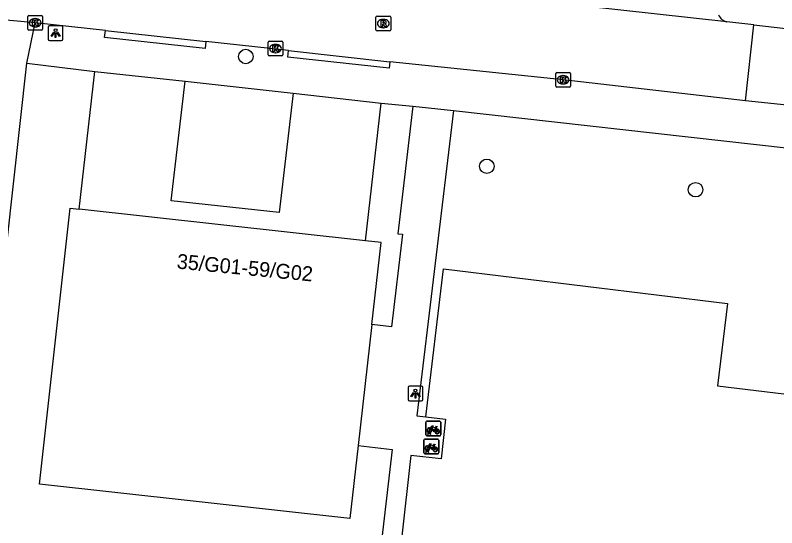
# Model space of a CAD drawing. Extents: x 161928 to 163055, y 386475 to 387428.
# Drawn here: x 162126.5 to 162177.9, y 387120.3 to 387155 of the extents above; entities that cross this region are included whole.
import ezdxf

# ---------------------------------------------------------------- set-up
doc = ezdxf.new("R2010")
doc.units = 0
for name, color, linetype in [('IMGEO_Boom', 7, 'Continuous'), ('IMGEO_Fietsenrek', 7, 'Continuous'), ('IMGEO_Groenvoorziening', 7, 'Continuous'), ('IMGEO_Kolk', 7, 'Continuous'), ('IMGEO_Lichtpunt', 7, 'Continuous'), ('IMGEO_Pand', 7, 'Continuous'), ('IMGEO_Pand_nummerreeks', 7, 'Continuous'), ('IMGEO_Rijbaan_lokaal_open', 7, 'Continuous'), ('IMGEO_Rioolput', 7, 'Continuous'), ('IMGEO_Voetpad_open', 7, 'Continuous')]:
    doc.layers.add(name, color=color, linetype=linetype)

msp = doc.modelspace()

# ---------------------------------------------------------------- linework, layer by layer
at = {"layer": 'IMGEO_Boom'}
for centre in [(162142.04, 387152.202), (162158.336, 387144.781), (162172.448, 387143.2)]:
    msp.add_circle(centre, 0.489, dxfattribs=at)
at = {"layer": 'IMGEO_Fietsenrek'}
for p, q in [((162154.218, 387126.633), (162154.218, 387127.474)), ((162154.218, 387127.474), (162154.218, 387126.633)), ((162154.293, 387127.558), (162155.134, 387127.558)), ((162155.134, 387127.558), (162154.293, 387127.558)), ((162155.218, 387127.483), (162155.218, 387126.642)), ((162155.218, 387126.642), (162155.218, 387127.483)), ((162154.905, 387127.107), (162154.941, 387127.012)), ((162155.143, 387126.558), (162154.302, 387126.558)), ((162154.302, 387126.558), (162155.143, 387126.558)), ((162154.345, 387126.642), (162154.384, 387126.802)), ((162154.379, 387126.642), (162154.345, 387126.642)), ((162154.414, 387126.79), (162154.379, 387126.642)), ((162154.456, 387126.814), (162154.455, 387126.818)), ((162154.497, 387126.642), (162154.463, 387126.784)), ((162154.487, 387126.825), (162154.488, 387126.818)), ((162154.495, 387126.788), (162154.53, 387126.642)), ((162154.53, 387126.642), (162154.497, 387126.642)), ((162154.083, 387125.421), (162154.083, 387126.262)), ((162154.083, 387126.262), (162154.083, 387125.421)), ((162154.158, 387126.346), (162154.999, 387126.346)), ((162154.999, 387126.346), (162154.158, 387126.346)), ((162155.083, 387126.271), (162155.083, 387125.43)), ((162155.083, 387125.43), (162155.083, 387126.271)), ((162154.21, 387125.43), (162154.249, 387125.59)), ((162154.244, 387125.43), (162154.21, 387125.43)), ((162154.279, 387125.578), (162154.244, 387125.43)), ((162154.321, 387125.602), (162154.32, 387125.606)), ((162154.362, 387125.43), (162154.328, 387125.572)), ((162154.352, 387125.613), (162154.353, 387125.606)), ((162154.36, 387125.576), (162154.395, 387125.43)), ((162154.395, 387125.43), (162154.362, 387125.43)), ((162154.77, 387125.895), (162154.806, 387125.8)), ((162155.008, 387125.346), (162154.167, 387125.346)), ((162154.167, 387125.346), (162155.008, 387125.346))]:
    msp.add_line(p, q, dxfattribs=at)
for points in [[(162154.552, 387127.032), (162154.5, 387126.942), (162154.46, 387126.917), (162154.461, 387126.964), (162154.516, 387127.058)], [(162154.531, 387127.084), (162154.626, 387127.248), (162154.712, 387127.234), (162154.714, 387127.225), (162154.658, 387127.214), (162154.631, 387127.169), (162154.887, 387127.128)], [(162154.827, 387126.84), (162154.777, 387126.84), (162154.586, 387127.091), (162154.567, 387127.059)], [(162154.874, 387127.103), (162154.617, 387127.144), (162154.6, 387127.115), (162154.767, 387126.895), (162154.874, 387127.103)], [(162154.922, 387127.005), (162154.892, 387127.082), (162154.783, 387126.864), (162154.826, 387126.864)], [(162154.856, 387126.864), (162154.976, 387126.863), (162154.932, 387126.977)], [(162154.952, 387126.984), (162155.007, 387126.839), (162154.857, 387126.839)], [(162154.887, 387127.128), (162154.912, 387127.177), (162154.906, 387127.181), (162154.883, 387127.185), (162154.871, 387127.192), (162154.87, 387127.195), (162154.872, 387127.2), (162154.967, 387127.185), (162154.969, 387127.175), (162154.959, 387127.162), (162154.947, 387127.156), (162154.933, 387127.162), (162154.905, 387127.107)], [(162154.396, 387125.872), (162154.491, 387126.036), (162154.577, 387126.022), (162154.579, 387126.013), (162154.523, 387126.002), (162154.496, 387125.957), (162154.752, 387125.916)], [(162154.739, 387125.891), (162154.482, 387125.932), (162154.465, 387125.903), (162154.632, 387125.683), (162154.739, 387125.891)], [(162154.752, 387125.916), (162154.777, 387125.965), (162154.771, 387125.969), (162154.748, 387125.973), (162154.736, 387125.98), (162154.735, 387125.983), (162154.737, 387125.988), (162154.832, 387125.973), (162154.834, 387125.963), (162154.824, 387125.95), (162154.812, 387125.944), (162154.798, 387125.95), (162154.77, 387125.895)], [(162154.417, 387125.82), (162154.365, 387125.73), (162154.325, 387125.705), (162154.326, 387125.752), (162154.381, 387125.846)], [(162154.692, 387125.628), (162154.642, 387125.628), (162154.451, 387125.879), (162154.432, 387125.847)], [(162154.787, 387125.793), (162154.757, 387125.87), (162154.648, 387125.652), (162154.691, 387125.652)], [(162154.721, 387125.652), (162154.841, 387125.651), (162154.797, 387125.765)], [(162154.817, 387125.772), (162154.872, 387125.627), (162154.722, 387125.627)]]:
    msp.add_lwpolyline(points, dxfattribs=at)
for centre, radius, start, end in [((162154.296, 387127.48), 0.0779, 92.4484, 184.2845), ((162154.296, 387127.48), 0.0779, 92.4484, 184.2845), ((162155.14, 387127.48), 0.0779, 2.4484, 94.2845), ((162155.14, 387127.48), 0.0779, 2.4484, 94.2845), ((162154.458, 387126.943), 0.159, 62.6766, 242.1369), ((162154.458, 387126.943), 0.129, 63.3192, 238.903), ((162154.458, 387126.943), 0.129, 283.6043, 43.4302), ((162154.458, 387126.943), 0.159, 283.5766, 46.6042), ((162154.985, 387126.859), 0.159, 113.3408, 178.3217), ((162154.985, 387126.859), 0.159, 187.0065, 105.7708), ((162154.985, 387126.859), 0.129, 113.923, 177.9556), ((162154.985, 387126.859), 0.129, 188.6715, 104.5883), ((162154.296, 387126.636), 0.0779, 182.4484, 274.2845), ((162154.296, 387126.636), 0.0779, 182.4484, 274.2845), ((162154.438, 387126.814), 0.0499, 12.8025, 158.6934), ((162154.458, 387126.943), 0.159, 253.9967, 271.7867), ((162154.438, 387126.814), 0.0174, 12.8025, 163.4502), ((162154.458, 387126.943), 0.129, 253.415, 269.0204), ((162155.14, 387126.636), 0.0779, 272.4484, 4.2845), ((162155.14, 387126.636), 0.0779, 272.4484, 4.2845), ((162154.161, 387126.268), 0.0779, 92.4484, 184.2845), ((162154.161, 387126.268), 0.0779, 92.4484, 184.2845), ((162155.005, 387126.268), 0.0779, 2.4484, 94.2845), ((162155.005, 387126.268), 0.0779, 2.4484, 94.2845), ((162154.161, 387125.424), 0.0779, 182.4484, 274.2845), ((162154.161, 387125.424), 0.0779, 182.4484, 274.2845), ((162154.323, 387125.731), 0.159, 62.6766, 242.1369), ((162154.323, 387125.731), 0.129, 63.3192, 238.903), ((162154.303, 387125.602), 0.0499, 12.8025, 158.6934), ((162154.323, 387125.731), 0.159, 253.9967, 271.7867), ((162154.303, 387125.602), 0.0174, 12.8025, 163.4502), ((162154.323, 387125.731), 0.129, 253.415, 269.0204), ((162154.323, 387125.731), 0.129, 283.6043, 43.4302), ((162154.323, 387125.731), 0.159, 283.5766, 46.6042), ((162154.85, 387125.647), 0.159, 113.3408, 178.3217), ((162154.85, 387125.647), 0.159, 187.0065, 105.7708), ((162154.85, 387125.647), 0.129, 113.923, 177.9556), ((162154.85, 387125.647), 0.129, 188.6715, 104.5883), ((162155.005, 387125.424), 0.0779, 272.4484, 4.2845), ((162155.005, 387125.424), 0.0779, 272.4484, 4.2845)]:
    msp.add_arc(centre, radius, start, end, dxfattribs=at)
at = {"layer": 'IMGEO_Groenvoorziening'}
msp.add_lwpolyline([(162154.203, 387127.848), (162155.402, 387137.861), (162174.608, 387135.503), (162173.926, 387129.945), (162180.477, 387129.142), (162179.565, 387121.698), (162182.791, 387121.303), (162181.309, 387109.194), (162185.131, 387108.727), (162184.179, 387100.935), (162179.719, 387101.481), (162178.823, 387093.771), (162172.783, 387094.444)], dxfattribs=at)
at = {"layer": 'IMGEO_Kolk'}
for p, q in [((162127.298, 387154.059), (162127.298, 387154.911)), ((162127.373, 387154.985), (162128.225, 387154.985)), ((162127.786, 387154.765), (162127.811, 387154.765)), ((162128.299, 387154.911), (162128.299, 387154.059)), ((162128.225, 387153.985), (162127.373, 387153.985)), ((162127.809, 387154.205), (162127.784, 387154.205)), ((162143.619, 387153.242), (162144.471, 387153.242)), ((162143.544, 387152.316), (162143.544, 387153.168)), ((162144.032, 387153.022), (162144.057, 387153.022)), ((162144.545, 387153.168), (162144.545, 387152.316)), ((162144.471, 387152.242), (162143.619, 387152.242)), ((162144.055, 387152.462), (162144.03, 387152.462)), ((162162.994, 387150.205), (162162.994, 387151.057)), ((162163.069, 387151.131), (162163.921, 387151.131)), ((162163.482, 387150.911), (162163.507, 387150.911)), ((162163.995, 387151.057), (162163.995, 387150.205)), ((162163.921, 387150.131), (162163.069, 387150.131)), ((162163.505, 387150.351), (162163.48, 387150.351))]:
    msp.add_line(p, q, dxfattribs=at)
for points in [[(162127.298, 387154.059), (162127.298, 387154.911)], [(162127.373, 387154.985), (162128.225, 387154.985)], [(162128.299, 387154.911), (162128.299, 387154.059)], [(162127.619, 387154.685), (162127.742, 387154.685), (162127.742, 387154.534), (162127.872, 387154.685), (162128.036, 387154.685), (162127.89, 387154.534), (162128.043, 387154.285), (162127.891, 387154.285), (162127.806, 387154.449), (162127.742, 387154.382), (162127.742, 387154.285), (162127.619, 387154.285), (162127.619, 387154.685)], [(162128.225, 387153.985), (162127.373, 387153.985)], [(162143.619, 387153.242), (162144.471, 387153.242)], [(162143.544, 387152.316), (162143.544, 387153.168)], [(162143.865, 387152.942), (162143.988, 387152.942), (162143.988, 387152.791), (162144.118, 387152.942), (162144.282, 387152.942), (162144.136, 387152.791), (162144.289, 387152.542), (162144.137, 387152.542), (162144.052, 387152.706), (162143.988, 387152.639), (162143.988, 387152.542), (162143.865, 387152.542), (162143.865, 387152.942)], [(162144.545, 387153.168), (162144.545, 387152.316)], [(162144.471, 387152.242), (162143.619, 387152.242)], [(162162.994, 387150.205), (162162.994, 387151.057)], [(162163.069, 387151.131), (162163.921, 387151.131)], [(162163.315, 387150.831), (162163.438, 387150.831), (162163.438, 387150.68), (162163.568, 387150.831), (162163.732, 387150.831), (162163.586, 387150.68), (162163.739, 387150.431), (162163.587, 387150.431), (162163.502, 387150.595), (162163.438, 387150.528), (162163.438, 387150.431), (162163.315, 387150.431), (162163.315, 387150.831)], [(162163.995, 387151.057), (162163.995, 387150.205)], [(162163.921, 387150.131), (162163.069, 387150.131)]]:
    msp.add_lwpolyline(points, dxfattribs=at)
for centre, start, end in [((162127.375, 387154.909), 91.552, 178.448), ((162127.375, 387154.909), 91.552, 178.448), ((162128.223, 387154.909), 1.552, 88.448), ((162128.223, 387154.909), 1.552, 88.448), ((162127.375, 387154.061), 181.552, 268.448), ((162127.375, 387154.061), 181.552, 268.448), ((162128.223, 387154.061), 271.552, 358.448), ((162128.223, 387154.061), 271.552, 358.448), ((162143.621, 387153.166), 91.552, 178.448), ((162143.621, 387153.166), 91.552, 178.448), ((162144.469, 387153.166), 1.552, 88.448), ((162144.469, 387153.166), 1.552, 88.448), ((162143.621, 387152.318), 181.552, 268.448), ((162143.621, 387152.318), 181.552, 268.448), ((162144.469, 387152.318), 271.552, 358.448), ((162144.469, 387152.318), 271.552, 358.448), ((162163.071, 387151.055), 91.552, 178.448), ((162163.071, 387151.055), 91.552, 178.448), ((162163.919, 387151.055), 1.552, 88.448), ((162163.919, 387151.055), 1.552, 88.448), ((162163.071, 387150.207), 181.552, 268.448), ((162163.071, 387150.207), 181.552, 268.448), ((162163.919, 387150.207), 271.552, 358.448), ((162163.919, 387150.207), 271.552, 358.448)]:
    msp.add_arc(centre, 0.0765, start, end, dxfattribs=at)
for centre, major_axis, ratio, start_param, end_param in [((162127.785, 387154.485), (-0.387, 0.002), 0.722429, 4.712389, 7.853982), ((162127.81, 387154.485), (-0.39, 0.002), 0.717154, 1.570796, 4.712389), ((162144.031, 387152.742), (-0.387, 0.002), 0.722429, 4.712389, 7.853982), ((162144.056, 387152.742), (-0.39, 0.002), 0.717154, 1.570796, 4.712389), ((162163.481, 387150.631), (-0.387, 0.002), 0.722429, 4.712389, 7.853982), ((162163.506, 387150.631), (-0.39, 0.002), 0.717154, 1.570796, 4.712389)]:
    msp.add_ellipse(centre, major_axis=major_axis, ratio=ratio, start_param=start_param, end_param=end_param, dxfattribs=at)
at = {"layer": 'IMGEO_Lichtpunt'}
for p, q in [((162129.585, 387154.281), (162128.777, 387154.281)), ((162129.585, 387154.281), (162128.777, 387154.281)), ((162128.683, 387154.186), (162128.683, 387153.379)), ((162128.683, 387154.186), (162128.683, 387153.379)), ((162129.679, 387153.379), (162129.679, 387154.186)), ((162129.679, 387153.379), (162129.679, 387154.186)), ((162128.777, 387153.285), (162129.585, 387153.285)), ((162128.777, 387153.285), (162129.585, 387153.285)), ((162153.011, 387129.823), (162153.011, 387129.016)), ((162153.011, 387129.823), (162153.011, 387129.016)), ((162153.913, 387129.918), (162153.105, 387129.918)), ((162153.913, 387129.918), (162153.105, 387129.918)), ((162154.007, 387129.016), (162154.007, 387129.823)), ((162154.007, 387129.016), (162154.007, 387129.823)), ((162153.105, 387128.922), (162153.913, 387128.922)), ((162153.105, 387128.922), (162153.913, 387128.922))]:
    msp.add_line(p, q, dxfattribs=at)
for points in [[(162129.057, 387153.85), (162129.096, 387153.822), (162128.908, 387153.56), (162128.87, 387153.587), (162129.057, 387153.85)], [(162129.159, 387153.802), (162129.206, 387153.802), (162129.206, 387153.48), (162129.159, 387153.48), (162129.159, 387153.802)], [(162129.269, 387153.822), (162129.307, 387153.849), (162129.494, 387153.587), (162129.455, 387153.559), (162129.269, 387153.822)], [(162153.385, 387129.487), (162153.424, 387129.459), (162153.236, 387129.197), (162153.198, 387129.224), (162153.385, 387129.487)], [(162153.487, 387129.439), (162153.534, 387129.439), (162153.534, 387129.117), (162153.487, 387129.117), (162153.487, 387129.439)], [(162153.597, 387129.459), (162153.635, 387129.486), (162153.822, 387129.224), (162153.783, 387129.196), (162153.597, 387129.459)]]:
    msp.add_lwpolyline(points, dxfattribs=at)
for centre in [(162129.182, 387153.984), (162153.51, 387129.621)]:
    msp.add_circle(centre, 0.0994, dxfattribs=at)
for centre, start, end in [((162128.777, 387154.186), 90, 180), ((162128.777, 387154.186), 90, 180), ((162129.585, 387154.186), 0, 90), ((162129.585, 387154.186), 0, 90), ((162128.777, 387153.379), 180, 270), ((162128.777, 387153.379), 180, 270), ((162129.585, 387153.379), 270, 0), ((162129.585, 387153.379), 270, 360), ((162153.105, 387129.823), 90, 180), ((162153.105, 387129.823), 90, 180), ((162153.913, 387129.823), 0, 90), ((162153.913, 387129.823), 0, 90), ((162153.105, 387129.016), 180, 270), ((162153.105, 387129.016), 180, 270), ((162153.913, 387129.016), 270, 0), ((162153.913, 387129.016), 270, 360)]:
    msp.add_arc(centre, 0.0946, start, end, dxfattribs=at)
at = {"layer": 'IMGEO_Pand'}
for points in [[(162149.642, 387125.907), (162149.082, 387120.965), (162128.095, 387123.286), (162130.158, 387141.956), (162130.784, 387141.887)], [(162150.127, 387139.752), (162130.784, 387141.887)], [(162150.568, 387134.085), (162151.196, 387139.634), (162150.127, 387139.752)], [(162150.568, 387134.085), (162149.642, 387125.907)]]:
    msp.add_lwpolyline(points, dxfattribs=at)
at = {"layer": 'IMGEO_Rijbaan_lokaal_open'}
for points in [[(162174.573, 387154.541), (162152.651, 387156.975)], [(162127.799, 387154.485), (162124.603, 387154.771)], [(162132.545, 387153.964), (162127.799, 387154.485)], [(162176.382, 387154.335), (162174.573, 387154.541)], [(162175.819, 387149.213), (162176.382, 387154.335)], [(162176.382, 387154.335), (162179.143, 387154.028)], [(162132.545, 387153.964), (162139.345, 387153.217)], [(162144.92, 387152.605), (162139.345, 387153.217)], [(162144.92, 387152.605), (162151.788, 387151.851)], [(162175.819, 387149.213), (162163.495, 387150.631), (162151.788, 387151.851)], [(162178.618, 387148.906), (162175.819, 387149.213)]]:
    msp.add_lwpolyline(points, dxfattribs=at)
at = {"layer": 'IMGEO_Rioolput'}
for p, q in [((162150.836, 387154.005), (162150.836, 387154.857)), ((162150.911, 387154.931), (162151.763, 387154.931)), ((162151.837, 387154.857), (162151.837, 387154.005)), ((162151.324, 387154.711), (162151.349, 387154.711)), ((162151.763, 387153.931), (162150.911, 387153.931)), ((162151.347, 387154.151), (162151.322, 387154.151))]:
    msp.add_line(p, q, dxfattribs=at)
for points in [[(162150.836, 387154.005), (162150.836, 387154.857)], [(162150.911, 387154.931), (162151.763, 387154.931)], [(162151.837, 387154.857), (162151.837, 387154.005)], [(162151.425, 387154.629), (162151.173, 387154.631), (162151.173, 387154.231)], [(162151.173, 387154.231), (162151.297, 387154.231), (162151.297, 387154.393), (162151.308, 387154.393)], [(162151.351, 387154.55), (162151.297, 387154.55), (162151.297, 387154.469)], [(162151.297, 387154.469), (162151.349, 387154.469)], [(162151.355, 387154.364), (162151.426, 387154.231), (162151.566, 387154.231), (162151.501, 387154.357)], [(162151.763, 387153.931), (162150.911, 387153.931)]]:
    msp.add_lwpolyline(points, dxfattribs=at)
for centre, radius, start, end in [((162150.913, 387154.855), 0.0765, 91.552, 178.448), ((162150.913, 387154.855), 0.0765, 91.552, 178.448), ((162151.761, 387154.855), 0.0765, 1.552, 88.448), ((162151.761, 387154.855), 0.0765, 1.552, 88.448), ((162151.307, 387154.34), 0.0533, 26.0293, 88.6989), ((162151.333, 387154.658), 0.19, 274.7715, 282.9687), ((162151.357, 387154.454), 0.0964, 77.0061, 93.1865), ((162151.371, 387154.511), 0.0378, 276.6634, 79.6772), ((162151.424, 387154.519), 0.109, 350.3612, 89.416), ((162151.422, 387154.519), 0.112, 277.5842, 350.9817), ((162151.406, 387154.304), 0.108, 29.5134, 73.7905), ((162150.913, 387154.007), 0.0765, 181.552, 268.448), ((162150.913, 387154.007), 0.0765, 181.552, 268.448), ((162151.761, 387154.007), 0.0765, 271.552, 358.448), ((162151.761, 387154.007), 0.0765, 271.552, 358.448)]:
    msp.add_arc(centre, radius, start, end, dxfattribs=at)
for centre, major_axis, ratio, start_param, end_param in [((162151.323, 387154.431), (-0.387, 0.002), 0.722429, 4.712389, 7.853982), ((162151.348, 387154.431), (-0.39, 0.002), 0.717154, 1.570796, 4.712389)]:
    msp.add_ellipse(centre, major_axis=major_axis, ratio=ratio, start_param=start_param, end_param=end_param, dxfattribs=at)
at = {"layer": 'IMGEO_Voetpad_open'}
for points in [[(162127.241, 387151.764), (162127.799, 387154.485)], [(162139.345, 387153.217), (162139.294, 387152.751), (162132.493, 387153.482), (162132.545, 387153.964)], [(162151.788, 387151.851), (162151.741, 387151.411), (162144.872, 387152.15), (162144.92, 387152.605)], [(162123.607, 387119.13), (162127.241, 387151.764)], [(162127.241, 387151.764), (162131.84, 387151.186)], [(162130.784, 387141.887), (162131.84, 387151.186)], [(162131.84, 387151.186), (162137.94, 387150.528)], [(162145.239, 387149.721), (162144.285, 387141.651), (162136.995, 387142.458), (162137.94, 387150.528)], [(162137.94, 387150.528), (162145.239, 387149.721)], [(162145.239, 387149.721), (162151.188, 387149.044)], [(162150.127, 387139.752), (162151.188, 387149.044)], [(162153.328, 387148.844), (162152.326, 387140.223), (162152.624, 387140.189), (162151.896, 387133.93), (162150.568, 387134.085)], [(162151.188, 387149.044), (162153.328, 387148.844)], [(162153.328, 387148.844), (162156.077, 387148.555)], [(162156.077, 387148.555), (162153.606, 387127.915), (162154.203, 387127.848)], [(162156.077, 387148.555), (162188.017, 387144.977)], [(162154.203, 387127.848), (162155.544, 387127.699), (162155.244, 387125.016), (162153.206, 387125.243), (162152.573, 387119.574), (162152.163, 387115.897)], [(162149.642, 387125.907), (162151.927, 387125.641), (162150.578, 387114.029), (162148.324, 387114.291), (162148.01, 387111.589), (162150.265, 387111.327), (162150.094, 387109.847), (162148.761, 387110.002), (162148.715, 387109.615)]]:
    msp.add_lwpolyline(points, dxfattribs=at)
msp.add_arc((162174.747, 387155.325), 0.803, 202.6326, 257.4588, dxfattribs=at)

# ---------------------------------------------------------------- texts
at = {"layer": 'IMGEO_Pand_nummerreeks'}
msp.add_text('35/G01-59/G02', height=1, rotation=354.4996, dxfattribs=at).set_placement((162137.346, 387137.877))

doc.saveas('drawing.dxf')
